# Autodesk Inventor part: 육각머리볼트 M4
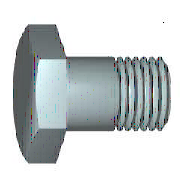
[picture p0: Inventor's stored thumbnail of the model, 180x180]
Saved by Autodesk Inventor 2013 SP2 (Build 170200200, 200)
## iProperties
IsCustomPart: 1
Created: 2012-02
Part Number: 육각머리볼트 M4
Material: 스테인리스강
Description: 6각 머리 볼트 및 6각 머리 나사
Document SubType Name: Modeling
Standard: KS B 1002
Designer: mduedu
Standards Organization: KS
Language: ko-KR
Size Designation: A + B M4 x 10
Categories: <MemberInstance><Categories><Category DisplayName="조임쇠" InternalName="e4da775c-781d-43d5-af7c-5136215cf5a6" Mnemonic="FSTN"><Category DisplayName="볼트" InternalN
Density: 8.08 g/cm^3
Mass: 1.91435 g
Surface Area: 2.70732 cm^2
Volume: 0.236925 cm^3
Author: mduedu
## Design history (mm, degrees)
sketch "스케치1"
  geometry: L1 (0, 2.94)-(0, 2); L2 (2.1, 2)-(10, 2); L3 (10, 2)-(10, 0); L4 (10, 0)-(-0.4, 0); L5 (-2.48, 0)-(12.08, 0) reference; L6 (-0.4, 0)-(-0.4, 2.94); L7 (-0.4, 2.94)-(0, 2.94); L8 (2.1, 2)-(1.67, 2); L9 (1.67, 2)-(0, 2); L10 (0, -0.588)-(0, 3.528) reference
  constraints: 16 end point, 2 collinear, 2 perpendicular, 1 parallel
  dimensions: "d0" = 10 distance between parallel lines of L3 L1 (= NLG); "d1" = 7.9 distance from line of L2.start L3 (= GEL); "d2" = 4 diameter of L2 L4 (= GD); "d9" = 0.4001 distance between parallel lines of L6 L1 (computed from SD); "d10" = 5.88 diameter of L7 L4 (= SD2); "d13" = 0.42952 distance of L2.start L8.end (computed from GAL); "d14" = 4 diameter of L9 L4 (= BDM)
revolve "본체" sketch "스케치1" stored, may be unused: angle "d12" = 90 deg
sketch "스케치2"
  geometry: L1 (0, 4.041)-(3.5, 2.021); L2 (3.5, 2.021)-(3.5, -2.021); L3 (3.5, -2.021)-(0, -4.041); L4 (0, -4.041)-(-3.5, -2.021); L5 (-3.5, -2.021)-(-3.5, 2.021); L6 (-3.5, 2.021)-(0, 4.041); 2 further points
  constraints: 12 end point, 1 coincident, 1 vertical, 11 other
  dimensions: "d11" = 7 distance between parallel lines of L5 L2 (= SW)
extrude "머리" join sketch "스케치2" distance "d3" = 2.4 (= KOH - SD); taper "d4" = 0 deg
sketch "스케치4"
  geometry: L1 (-2.8, 3.5)-(-2.8, 4.041); L2 (-2.8, 4.041)-(-2.487, 4.041); L3 (-2.487, 4.041)-(-2.8, 3.5); L4 (-3.28, 0)-(0.08, 0) reference; L5 (-0.4, 4.041)-(-2.8, 4.041) reference; L6 (-2.8, 2.021)-(-2.8, 4.041) reference
  constraints: 6 end point, 2 collinear, 1 perpendicular, 1 vertical
  dimensions: "d5" = 30 deg angle of L3 L1 (= ANG1); "d19" = 7 diameter of L1.start L4 (= SW0)
revolve "모따기1" sketch "스케치4" stored, may be unused: angle "d21" = 90 deg
workplane "Work Plane1"
body "Solid1"
feature "스레드" dims "d15" = 7.9 (= GEL), "d16" = 0
chamfer "모따기2" distance "d6" = 0.42941 (= -0.5 x SPD + 0.5 x GD); stored, may be unused: second distance "d7" = 0.42952 (computed from GUL), angle "d55" = 45 deg
other parameters: "NLG" = 10 [user parameter; used in 1 equation term], "GD" = 4 (= NND) [user parameter; used in 2 equation terms], "BDM" = 4 (= NND) [user parameter; used in 1 equation term], "KOH" = 2.8 [user parameter; used in 1 equation term], "GEL" = 7.9 [user parameter; used in 2 equation terms], "SW" = 7 [user parameter; used in 3 equation terms], "SW0" = 7 (= SW) [user parameter; used in 1 equation term], "SPD" = 3.14117 (= NND - 1.2269 x PTC) [user parameter; used in 1 equation term], "SD2" = 5.88 (= SDH) [user parameter; used in 1 equation term], "SD" = 0.4 [user parameter; used in 2 equation terms], "ANG1" = 30 deg [user parameter; used in 1 equation term], "GAL" = 0.42941 (= 0.61345 x PTC) [user parameter; used in 1 equation term], "GUL" = 0.42941 (= 0.61345 x PTC) [user parameter; used in 1 equation term], "d8" = 0, "RR" = 0.2 [user parameter], "d57" = 0, "d58" = 0, "TPU" = 14.28571 (computed from PTC) [user parameter], "GD1" = 3.14117 (= THREADDIA - 1.2269 x PTC) [user parameter], "THREADDIA" = 4 [user parameter; used in 1 equation term], "SDH" = 5.88 [user parameter; used in 1 equation term], "SDHG" = 2.1 [user parameter], "TOA" = 30 deg [user parameter], "PTC" = 0.7 [user parameter; used in 5 equation terms], "NND" = 4 [user parameter; used in 3 equation terms], "E0" = 8.085 (= 1.155 x SW) [user parameter]
